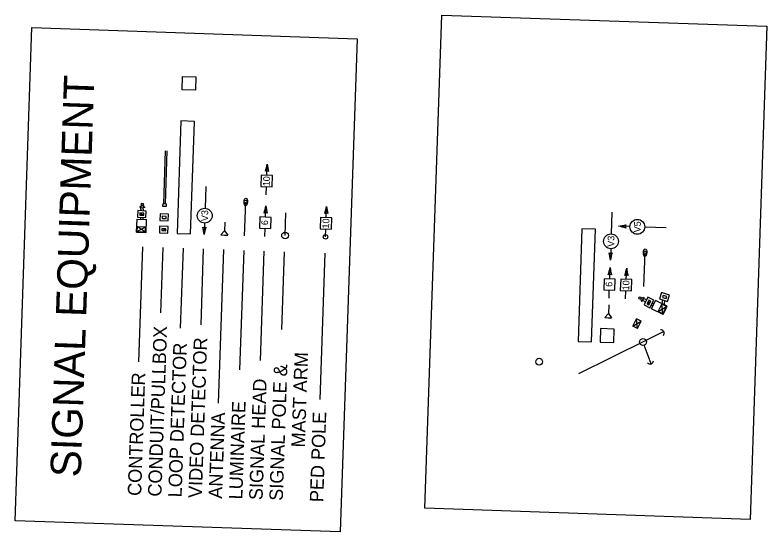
# Model space of a CAD drawing. Extents: x 982100 to 1292532, y 220574 to 1843876.
# Drawn here: x 992766.5 to 993100.8, y 1843646.6 to 1843876.1 of the extents above; entities that cross this region are included whole.
import ezdxf

# ---------------------------------------------------------------- set-up
doc = ezdxf.new("R2010")
doc.units = 0
for name, color, linetype in [('Default', 7, 'Continuous'), ('R_Existing Signal', 7, 'Continuous'), ('V-SIGNAL-CONDUIT', 7, 'Continuous'), ('V-SIGNAL-CONTROLLER', 7, 'Continuous'), ('V-SIGNAL-HEAD', 7, 'Continuous'), ('V-SIGNAL-HEAD-MOT', 7, 'Continuous'), ('V-SIGNAL-LOOP', 7, 'Continuous'), ('V-SIGNAL-LOOP-MOT', 7, 'Continuous'), ('V-SIGNAL-MAST', 7, 'Continuous'), ('V-SIGNAL-POLE', 7, 'Continuous'), ('V-SIGNAL-POLE-MOT', 7, 'Continuous')]:
    doc.layers.add(name, color=color, linetype=linetype)

msp = doc.modelspace()

# ---------------------------------------------------------------- linework, layer by layer
at = {"layer": 'Default'}
for p, q in [((992821.62, 1843722.04), (992823.37, 1843773.17)), ((992831.37, 1843743.86), (992832.37, 1843772.86)), ((992840.15, 1843737.13), (992841.36, 1843772.55)), ((992849.2, 1843738.6), (992850.36, 1843772.24)), ((992857.01, 1843703.76), (992859.35, 1843771.93)), ((992866.52, 1843718.5), (992868.35, 1843771.62)), ((992875.68, 1843722.76), (992877.34, 1843771.31)), ((992885.15, 1843736.48), (992886.34, 1843771.01)), ((992902.1, 1843705.37), (992904.32, 1843770.39))]:
    msp.add_line(p, q, dxfattribs=at)
at = {"layer": 'R_Existing Signal'}
for p, q in [((993041.21, 1843737.91), (993042.83, 1843741.2)), ((993043.23, 1843736.92), (993042.83, 1843741.2)), ((993044.85, 1843740.21), (993042.83, 1843741.2)), ((993041.21, 1843737.91), (993044.85, 1843740.21)), ((993043.23, 1843736.92), (993041.21, 1843737.91)), ((993043.23, 1843736.92), (993044.85, 1843740.21))]:
    msp.add_line(p, q, dxfattribs=at)
msp.add_circle((992999.5, 1843722.16), 1.5, dxfattribs=at)
at = {"layer": 'V-SIGNAL-CONDUIT'}
for p, q in [((992832.66, 1843792.2), (992833.47, 1843815.84)), ((992833.4, 1843792.17), (992834.21, 1843815.81)), ((992822.06, 1843791.12), (992822.02, 1843790.62)), ((992822.56, 1843791.08), (992822.06, 1843791.12)), ((992822.59, 1843791.58), (992822.52, 1843790.59)), ((992822.59, 1843791.58), (992823.59, 1843791.51)), ((992823.59, 1843791.51), (992823.52, 1843790.52)), ((992823.55, 1843791.02), (992824.05, 1843790.98)), ((992824.05, 1843790.98), (992824.02, 1843790.48)), ((992832.16, 1843792.21), (992832.12, 1843791.3)), ((992832.12, 1843791.3), (992833.87, 1843791.24)), ((992833.9, 1843792.15), (992832.16, 1843792.21)), ((992833.87, 1843791.24), (992833.9, 1843792.15)), ((992821.1, 1843789.25), (992820.96, 1843786.34)), ((992824.84, 1843789.08), (992821.1, 1843789.25)), ((992822.05, 1843788.21), (992822.01, 1843787.29)), ((992823.8, 1843788.12), (992822.05, 1843788.21)), ((992822.05, 1843788.21), (992823.75, 1843787.21)), ((992822.5, 1843789.89), (992822.52, 1843790.59)), ((992822.5, 1843789.89), (992822.5, 1843789.19)), ((992822.52, 1843790.59), (992823.52, 1843790.52)), ((992823.5, 1843789.86), (992823.52, 1843790.55)), ((992823.5, 1843789.86), (992823.5, 1843789.15)), ((992823.75, 1843787.21), (992823.8, 1843788.12)), ((992824.71, 1843786.16), (992824.84, 1843789.08)), ((992831, 1843787.78), (992830.9, 1843784.86)), ((992834.75, 1843787.65), (992831, 1843787.78)), ((992834.65, 1843784.73), (992834.75, 1843787.65)), ((992820.96, 1843786.34), (992824.71, 1843786.16)), ((992822.01, 1843787.29), (992823.75, 1843787.21)), ((992822.34, 1843786.27), (992822.35, 1843785.43)), ((992823.34, 1843786.23), (992823.34, 1843785.4)), ((992830.9, 1843784.86), (992834.65, 1843784.73)), ((992831.97, 1843786.74), (992831.94, 1843785.83)), ((992831.94, 1843785.83), (992833.69, 1843785.77)), ((992833.72, 1843786.68), (992831.97, 1843786.74)), ((992833.69, 1843785.77), (992833.72, 1843786.68)), ((992830.81, 1843782.31), (992830.71, 1843779.39)), ((992834.56, 1843782.18), (992830.81, 1843782.31)), ((992831.78, 1843781.27), (992831.75, 1843780.36)), ((992831.75, 1843780.36), (992833.53, 1843781.21)), ((992833.53, 1843781.21), (992831.78, 1843781.27)), ((992833.5, 1843780.3), (992833.53, 1843781.21)), ((992834.46, 1843779.26), (992834.56, 1843782.18)), ((992830.71, 1843779.39), (992834.46, 1843779.26)), ((992831.75, 1843780.36), (992833.5, 1843780.3)), ((993045.53, 1843750.41), (993045.76, 1843750.85)), ((993045.76, 1843750.85), (993046.2, 1843750.62)), ((993047.83, 1843750.8), (993046.13, 1843747.45)), ((993050.43, 1843749.48), (993047.83, 1843750.8)), ((993053.92, 1843752.86), (993053.01, 1843750.09)), ((993057.48, 1843751.7), (993053.92, 1843752.86)), ((993054.56, 1843751.6), (993054.27, 1843750.73)), ((993054.27, 1843750.73), (993055.94, 1843750.19)), ((993056.22, 1843751.06), (993054.56, 1843751.6)), ((993055.94, 1843750.19), (993056.22, 1843751.06)), ((993056.58, 1843748.93), (993057.48, 1843751.7)), ((993044.62, 1843749.77), (993045.09, 1843750.65)), ((993044.62, 1843749.77), (993045.5, 1843749.3)), ((993045.06, 1843749.53), (993044.82, 1843749.09)), ((993044.82, 1843749.09), (993045.26, 1843748.85)), ((993045.09, 1843750.65), (993045.97, 1843750.18)), ((993045.5, 1843749.3), (993045.97, 1843750.18)), ((993046.12, 1843748.99), (993045.5, 1843749.3)), ((993046.56, 1843749.89), (993045.94, 1843750.19)), ((993046.12, 1843748.99), (993046.77, 1843748.7)), ((993046.13, 1843747.45), (993048.73, 1843746.13)), ((993046.56, 1843749.89), (993047.21, 1843749.6)), ((993048.27, 1843749.45), (993047.48, 1843747.89)), ((993047.48, 1843747.89), (993049.08, 1843749.04)), ((993047.48, 1843747.89), (993048.29, 1843747.48)), ((993049.08, 1843749.04), (993048.27, 1843749.45)), ((993048.29, 1843747.48), (993049.08, 1843749.04)), ((993048.73, 1843746.13), (993050.43, 1843749.48)), ((993049.81, 1843748.26), (993050.57, 1843747.92)), ((993053.01, 1843750.09), (993056.58, 1843748.93)), ((993054.31, 1843749.67), (993054.06, 1843748.01)), ((993055.28, 1843749.35), (993055.01, 1843747.66)), ((993049.36, 1843747.37), (993050.13, 1843747.03))]:
    msp.add_line(p, q, dxfattribs=at)
for centre in [(992823.1, 1843792.11), (993044.34, 1843750.45)]:
    msp.add_circle(centre, 0.5, dxfattribs=at)
at = {"layer": 'V-SIGNAL-CONTROLLER'}
for p, q in [((992820.6, 1843779.74), (992820.79, 1843785.48)), ((992820.79, 1843785.48), (992824.96, 1843785.34)), ((992824.76, 1843779.6), (992824.96, 1843785.34)), ((992820.85, 1843779.98), (992820.93, 1843782.23)), ((992820.85, 1843779.98), (992824.6, 1843782.1)), ((992820.93, 1843782.23), (992824.6, 1843782.1)), ((992820.93, 1843782.23), (992824.52, 1843779.85)), ((992824.52, 1843779.85), (992824.6, 1843782.1)), ((992820.6, 1843779.74), (992824.76, 1843779.6)), ((992820.85, 1843779.98), (992824.52, 1843779.85)), ((993049.45, 1843745.63), (993051.28, 1843749.37)), ((993056.44, 1843746.84), (993051.28, 1843749.37)), ((993052.47, 1843744.42), (993054.09, 1843747.72)), ((993056.11, 1843746.73), (993054.09, 1843747.72)), ((993054.49, 1843743.43), (993054.09, 1843747.72)), ((993054.61, 1843743.1), (993049.45, 1843745.63)), ((993052.47, 1843744.42), (993056.11, 1843746.73)), ((993054.49, 1843743.43), (993052.47, 1843744.42)), ((993054.49, 1843743.43), (993056.11, 1843746.73)), ((993054.61, 1843743.1), (993056.44, 1843746.84))]:
    msp.add_line(p, q, dxfattribs=at)
for points in [[(992948.75, 1843657.07), (992956.26, 1843876.11), (993100.77, 1843871.16), (993093.26, 1843652.11)], [(992766.54, 1843651.51), (992774.05, 1843870.56), (992918.56, 1843865.6), (992911.04, 1843646.56)]]:
    msp.add_lwpolyline(points, close=True, dxfattribs=at)
at = {"layer": 'V-SIGNAL-HEAD'}
for p, q in [((992878.49, 1843804.91), (992878.66, 1843809.9)), ((992851.3, 1843799.9), (992850.98, 1843790.3)), ((992878.2, 1843796.34), (992878.32, 1843799.91)), ((992868.57, 1843778.09), (992869.08, 1843793.08)), ((992877.86, 1843786.35), (992878.03, 1843791.34)), ((992904.86, 1843786.15), (992905.03, 1843791.15)), ((992859.77, 1843784.2), (992859.64, 1843780.26)), ((992850.75, 1843783.7), (992850.58, 1843778.71)), ((992877.57, 1843777.78), (992877.69, 1843781.35)), ((992904.57, 1843777.59), (992904.69, 1843781.15)), ((992858.07, 1843778.45), (992859.57, 1843778.4)), ((992859.57, 1843778.4), (992861.07, 1843778.35))]:
    msp.add_line(p, q, dxfattribs=at)
for points in [[(992875.82, 1843800), (992880.82, 1843799.82), (992880.99, 1843804.82), (992875.99, 1843804.99)], [(992875.19, 1843781.44), (992880.19, 1843781.27), (992880.36, 1843786.26), (992875.36, 1843786.44)], [(992902.19, 1843781.24), (992907.19, 1843781.07), (992907.36, 1843786.07), (992902.36, 1843786.24)]]:
    msp.add_lwpolyline(points, close=True, dxfattribs=at)
msp.add_lwpolyline([(992858.07, 1843778.45), (992859.64, 1843780.26), (992861.07, 1843778.35)], dxfattribs=at)
for centre, radius in [((992869.08, 1843793.08), 0.75), ((992850.86, 1843787), 3.3)]:
    msp.add_circle(centre, radius, dxfattribs=at)
for centre, radius, start, end in [((992854.78, 1843814.35), 24.29, 341.7116, 349.4497), ((992902.79, 1843812.72), 24.29, 186.6664, 194.4045), ((992878.51, 1843805.56), 1.34, 56.2107, 119.9054), ((992854.15, 1843795.79), 24.29, 341.7116, 349.4497), ((992902.16, 1843794.16), 24.29, 186.6664, 194.4045), ((992881.15, 1843795.59), 24.29, 341.7116, 349.4497), ((992929.16, 1843793.97), 24.29, 186.6664, 194.4045), ((992877.88, 1843787.01), 1.34, 56.2107, 119.9054), ((992904.89, 1843786.81), 1.34, 56.2107, 119.9054), ((992850.73, 1843783.05), 1.34, 236.1974, 299.892), ((992826.45, 1843775.9), 24.29, 6.653, 14.3911), ((992874.46, 1843774.26), 24.29, 161.6982, 169.4364)]:
    msp.add_arc(centre, radius, start, end, dxfattribs=at)
msp.add_ellipse((992869.08, 1843793.08), major_axis=(-0.06, -1.7), ratio=0.441176, dxfattribs=at)
at = {"layer": 'V-SIGNAL-HEAD-MOT'}
for p, q in [((993031.88, 1843788.51), (993031.56, 1843778.91)), ((993039.84, 1843782.17), (993034.84, 1843782.34)), ((993056.03, 1843781.62), (993046.43, 1843781.95)), ((993031.33, 1843772.32), (993031.16, 1843767.32)), ((993046.08, 1843755.61), (993046.6, 1843770.59)), ((993030.87, 1843758.94), (993031.04, 1843763.94)), ((993038.25, 1843758.69), (993038.42, 1843763.68)), ((993030.58, 1843750.38), (993030.7, 1843753.95)), ((993037.96, 1843750.12), (993038.08, 1843753.69)), ((993030.44, 1843747.49), (993030.3, 1843743.55)), ((993028.74, 1843741.75), (993030.24, 1843741.7)), ((993030.24, 1843741.7), (993031.74, 1843741.64))]:
    msp.add_line(p, q, dxfattribs=at)
for points in [[(993028.2, 1843754.03), (993033.2, 1843753.86), (993033.37, 1843758.86), (993028.37, 1843759.03)], [(993035.58, 1843753.78), (993040.58, 1843753.61), (993040.75, 1843758.6), (993035.75, 1843758.78)]]:
    msp.add_lwpolyline(points, close=True, dxfattribs=at)
msp.add_lwpolyline([(993028.74, 1843741.75), (993030.3, 1843743.55), (993031.74, 1843741.64)], dxfattribs=at)
for centre, radius in [((993043.13, 1843782.06), 3.3), ((993031.44, 1843775.61), 3.3), ((993046.6, 1843770.59), 0.75)]:
    msp.add_circle(centre, radius, dxfattribs=at)
for centre, radius, start, end in [((993032.03, 1843806.47), 24.29, 276.6503, 284.3884), ((993030.39, 1843758.46), 24.29, 71.6955, 79.4337), ((993039.18, 1843782.2), 1.34, 146.1947, 209.8893), ((993031.31, 1843771.66), 1.34, 236.1974, 299.892), ((993007.03, 1843764.51), 24.29, 6.653, 14.3911), ((993055.04, 1843762.87), 24.29, 161.6982, 169.4364), ((993007.16, 1843768.39), 24.29, 341.7116, 349.4497), ((993030.89, 1843759.6), 1.34, 56.2107, 119.9054), ((993055.17, 1843766.76), 24.29, 186.6664, 194.4045), ((993014.54, 1843768.13), 24.29, 341.7116, 349.4497), ((993062.55, 1843766.5), 24.29, 186.6664, 194.4045), ((993038.27, 1843759.35), 1.34, 56.2107, 119.9054)]:
    msp.add_arc(centre, radius, start, end, dxfattribs=at)
msp.add_ellipse((993046.6, 1843770.59), major_axis=(-0.06, -1.7), ratio=0.441176, dxfattribs=at)
at = {"layer": 'V-SIGNAL-LOOP'}
for points in [[(992846.97, 1843848.68), (992846.77, 1843842.69), (992840.77, 1843842.89), (992840.98, 1843848.89)], [(992846.3, 1843828.89), (992840.3, 1843829.09), (992838.59, 1843779.12), (992844.58, 1843778.92)]]:
    msp.add_lwpolyline(points, close=True, dxfattribs=at)
at = {"layer": 'V-SIGNAL-LOOP-MOT'}
for points in [[(993024.55, 1843780.95), (993018.55, 1843781.15), (993016.84, 1843731.18), (993022.84, 1843730.98)], [(993026.65, 1843730.85), (993032.64, 1843730.64), (993032.85, 1843736.64), (993026.85, 1843736.84)]]:
    msp.add_lwpolyline(points, close=True, dxfattribs=at)
at = {"layer": 'V-SIGNAL-POLE'}
msp.add_line((992886.58, 1843778.2), (992886.93, 1843788.25), dxfattribs=at)
for centre, radius in [((992886.58, 1843778.2), 1.5), ((992904.57, 1843777.59), 1)]:
    msp.add_circle(centre, radius, dxfattribs=at)
at = {"layer": 'V-SIGNAL-POLE-MOT'}
for p, q in [((993054.96, 1843735.51), (993047, 1843731.58)), ((993047, 1843731.58), (993016.94, 1843716.76)), ((993049.35, 1843721.23), (993046.19, 1843729.52))]:
    msp.add_line(p, q, dxfattribs=at)
msp.add_circle((993045.66, 1843730.92), 1.5, dxfattribs=at)
for centre, start, end in [((993053.61, 1843734.84), 318.748, 93.748), ((993048.82, 1843722.63), 223.368, 358.368)]:
    msp.add_arc(centre, 1.5, start, end, dxfattribs=at)

# ---------------------------------------------------------------- texts
at = {"layer": 'Default'}
msp.add_text('SIGNAL EQUIPMENT', height=13.5, rotation=88.0361, dxfattribs=at).set_placement((992795.71, 1843670.67))
at = {"layer": 'V-SIGNAL-HEAD'}
for s, rotation, p in [('10', 88.0961, (992879.74, 1843800.01)), ('V3', 88.708, (992852.29, 1843784.54)), ('6', 88.1517, (992878.99, 1843782.77)), ('10', 88.0961, (992906.11, 1843781.26))]:
    msp.add_text(s, height=3, rotation=rotation, dxfattribs=at).set_placement(p)
at = {"layer": 'V-SIGNAL-HEAD-MOT'}
for s, rotation, p in [('V5', 87.7469, (993044.56, 1843779.54)), ('V3', 88.708, (993032.87, 1843773.15)), ('6', 88.1517, (993032, 1843755.37)), ('10', 88.0961, (993039.5, 1843753.8))]:
    msp.add_text(s, height=3, rotation=rotation, dxfattribs=at).set_placement(p)
at = {"layer": 'V-SIGNAL-MAST'}
for s, p in [('CONDUIT/PULLBOX', (992831.57, 1843662.17)), ('VIDEO DETECTOR', (992849.56, 1843661.55)), ('LOOP DETECTOR', (992840.57, 1843661.86)), ('MAST ARM', (992895.36, 1843684)), ('SIGNAL POLE &', (992885.54, 1843660.32)), ('CONTROLLER', (992822.58, 1843662.48)), ('SIGNAL HEAD', (992876.55, 1843660.63)), ('LUMINAIRE', (992867.55, 1843660.94)), ('ANTENNA', (992858.56, 1843661.24)), ('PED POLE', (992903.53, 1843659.7))]:
    msp.add_text(s, height=6, rotation=88.0361, dxfattribs=at).set_placement(p)

doc.saveas('drawing.dxf')
